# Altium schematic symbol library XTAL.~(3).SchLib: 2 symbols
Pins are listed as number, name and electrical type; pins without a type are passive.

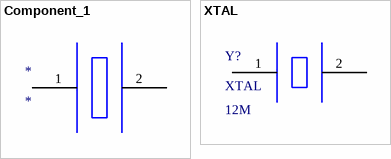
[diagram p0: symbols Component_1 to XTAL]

## Component_1
designator *
pins: 1, 2

## XTAL
designator Y?  XTAL: 12M
footprint XTAL
pins: 1, 2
